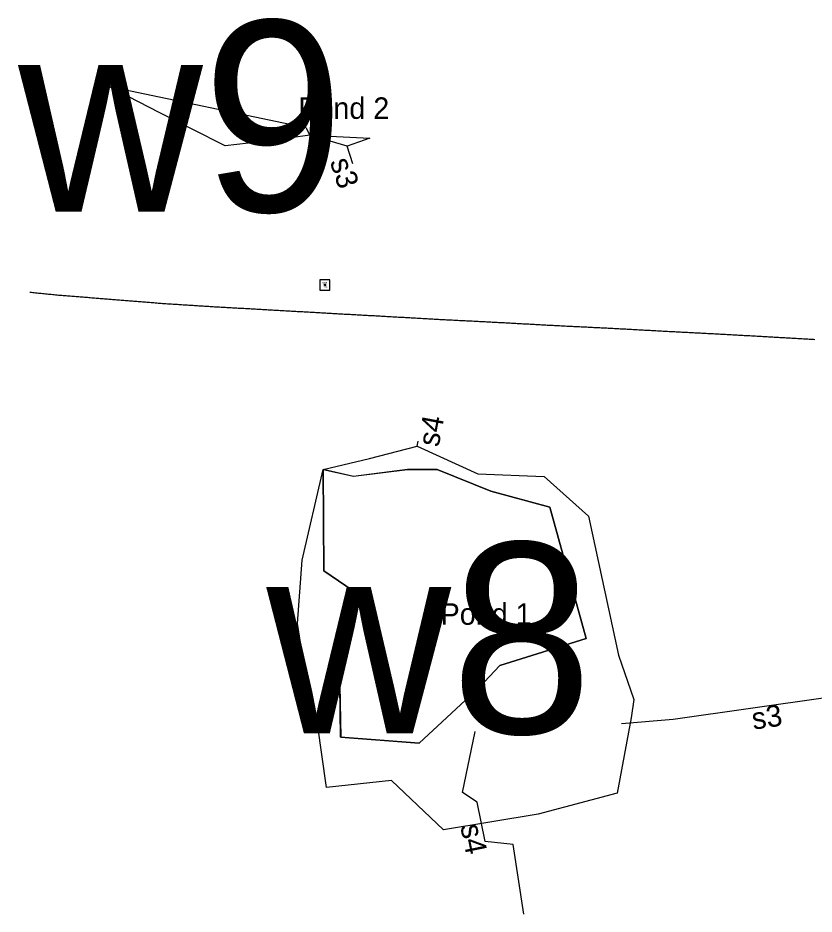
# Model space of a CAD drawing. Extents: x 205929 to 2357175, y -1785700 to 846739.
# Drawn here: x 2023790 to 2024346, y 813219 to 813844 of the extents above; entities that cross this region are included whole.
import ezdxf

# ---------------------------------------------------------------- set-up
doc = ezdxf.new("R2010")
doc.units = 0
for name, color, linetype in [('Default', 7, 'Continuous'), ('RD_EV_JTrib', 7, 'Continuous'), ('RD_EV_JW', 7, 'Continuous'), ('RD_EV_OWater', 7, 'Continuous'), ('RD_EV_TX', 7, 'Continuous'), ('RD_HC_Survey', 7, 'Continuous'), ('RD_HC_txCode', 7, 'Continuous'), ('RD_Sketch1', 7, 'Continuous'), ('RD_SMD_Locator', 7, 'Continuous')]:
    doc.layers.add(name, color=color, linetype=linetype)

# ---------------------------------------------------------------- blocks, each defined once
blk = doc.blocks.new('POL0003H')
at = {"layer": 'Default'}
blk.add_lwpolyline([(-28.23, 38.57), (-28.1, 20.59), (-21.57, 16.18), (-25.28, 0.31), (-25.1, -8.86), (-11.17, -9.92), (-0.58, -0.04), (3.12, 3.84), (18.42, 8.6), (11.94, 31.88), (1.53, 34.7), (-7.99, 38.58), (-13.28, 38.58), (-22.81, 37.35), (-28.23, 38.57), (-19.99, 40.51), (-11.56, 42.69), (-0.77, 37.81), (10.93, 37.3), (18.79, 30.28), (24.11, 5.68), (26.83, -2.21), (26.35, -5.46), (23.89, -18.77), (9.88, -22.48), (-6.88, -25.3), (-16.09, -16.51), (-27.63, -17.76), (-29.2, -6.5), (-31.05, 0.48), (-32.74, 11.27), (-31.92, 22.52)], close=True, dxfattribs=at)
blk = doc.blocks.new('POL0003I')
at = {"layer": 'Default'}
blk.add_lwpolyline([(16.05, -2.43), (9.29, -3.4), (1.03, -4.35), (-10.68, 1.57), (-19.69, 6.23), (15.36, -1.05)], close=True, dxfattribs=at)
blk = doc.blocks.new('ARC0002Y')
at = {"layer": 'Default'}
blk.add_lwpolyline([(30.39, -22.08), (18.78, -14.59), (8.16, -8.4), (4.67, 3.39), (-5.94, -4.32), (-33.35, -8.21), (-42.48, -8.95)], dxfattribs=at)
blk = doc.blocks.new('ARC0002Z')
at = {"layer": 'Default'}
blk.add_lwpolyline([(7.2, -14.7), (5.34, -2.35), (0.37, -1.82), (-1.05, 5.12), (-3.63, 6.86), (-1.37, 17.63)], dxfattribs=at)
blk = doc.blocks.new('ARC00030')
at = {"layer": 'Default'}
blk.add_lwpolyline([(-0.09, -0.46), (0.09, 0.46)], dxfattribs=at)
blk = doc.blocks.new('ARC00031')
at = {"layer": 'Default'}
blk.add_lwpolyline([(0.5, -1.54), (-0.5, 1.54)], dxfattribs=at)
blk = doc.blocks.new('POL0004D')
at = {"layer": 'Default'}
blk.add_lwpolyline([(0.86, -1.14), (-5.76, 0.83), (4.9, 0.31)], close=True, dxfattribs=at)
blk = doc.blocks.new('POL0004C')
at = {"layer": 'Default'}
blk.add_lwpolyline([(-20.42, 22.04), (-15, 20.82), (-5.48, 22.05), (-0.19, 22.05), (9.34, 18.17), (19.75, 15.35), (26.22, -7.93), (10.93, -12.7), (7.22, -16.58), (-3.36, -26.46), (-17.3, -25.4), (-17.47, -16.23), (-13.77, -0.35), (-20.3, 4.06)], close=True, dxfattribs=at)

msp = doc.modelspace()

# ---------------------------------------------------------------- linework, layer by layer
at = {"layer": 'RD_HC_Survey'}
msp.add_lwpolyline([(2024007.91, 813661.05), (2024000.84, 813661.05), (2024000.84, 813653.98), (2024007.91, 813653.98)], close=True, dxfattribs=at)
msp.add_circle((2024004.38, 813657.52), 0.5, dxfattribs=at)
at = {"layer": 'RD_Sketch1'}
msp.add_lwpolyline([(2023798.58, 813652.51), (2023799.57, 813652.41), (2023800.57, 813652.31), (2023801.56, 813652.21), (2023802.56, 813652.11), (2023803.55, 813652.01), (2023804.55, 813651.91), (2023805.54, 813651.81), (2023806.53, 813651.71), (2023807.53, 813651.61), (2023808.52, 813651.51), (2023809.52, 813651.41), (2023810.51, 813651.31), (2023811.51, 813651.21), (2023812.5, 813651.11), (2023813.5, 813651.01), (2023814.49, 813650.91), (2023815.49, 813650.81), (2023816.48, 813650.71), (2023817.48, 813650.61), (2023818.47, 813650.51), (2023818.77, 813650.48), (2023819.77, 813650.4), (2023820.76, 813650.32), (2023821.76, 813650.24), (2023822.76, 813650.16), (2023823.75, 813650.08), (2023824.75, 813650), (2023825.75, 813649.92), (2023826.74, 813649.84), (2023827.74, 813649.76), (2023828.74, 813649.68), (2023829.73, 813649.6), (2023830.73, 813649.52), (2023831.73, 813649.44), (2023832.72, 813649.37), (2023833.72, 813649.29), (2023834.72, 813649.21), (2023835.71, 813649.13), (2023836.71, 813649.05), (2023837.71, 813648.97), (2023838.7, 813648.89), (2023839.7, 813648.81), (2023840.7, 813648.73), (2023841.69, 813648.65), (2023842.69, 813648.57), (2023843.69, 813648.49), (2023844.68, 813648.41), (2023845.68, 813648.33), (2023846.68, 813648.25), (2023847.67, 813648.17), (2023848.67, 813648.09), (2023849.67, 813648.01), (2023850.66, 813647.94), (2023851.66, 813647.86), (2023852.66, 813647.78), (2023853.65, 813647.7), (2023854.18, 813647.65), (2023855.18, 813647.57), (2023856.18, 813647.49), (2023857.17, 813647.41), (2023858.17, 813647.33), (2023859.17, 813647.25), (2023860.16, 813647.17), (2023861.16, 813647.09), (2023861.16, 813647.09), (2023862.16, 813647.01), (2023863.15, 813646.93), (2023864.15, 813646.85), (2023865.15, 813646.77), (2023866.14, 813646.69), (2023867.14, 813646.61), (2023868.13, 813646.53), (2023869.13, 813646.45), (2023870.13, 813646.37), (2023871.12, 813646.29), (2023872.12, 813646.21), (2023873.12, 813646.13), (2023874.11, 813646.05), (2023875.11, 813645.97), (2023876.11, 813645.89), (2023877.1, 813645.81), (2023878.1, 813645.73), (2023879.1, 813645.65), (2023880.09, 813645.57), (2023881.09, 813645.49), (2023882.09, 813645.41), (2023883.08, 813645.33), (2023884.08, 813645.25), (2023885.08, 813645.17), (2023886.07, 813645.09), (2023887.07, 813645.01), (2023888.06, 813644.93), (2023889.06, 813644.85), (2023890.06, 813644.77), (2023891.05, 813644.69), (2023891.47, 813644.65), (2023892.47, 813644.59), (2023893.47, 813644.53), (2023894.47, 813644.46), (2023895.46, 813644.4), (2023896.46, 813644.34), (2023897.46, 813644.27), (2023898.46, 813644.21), (2023899.45, 813644.15), (2023900.45, 813644.08), (2023901.45, 813644.02), (2023902.45, 813643.96), (2023903.45, 813643.89), (2023904.44, 813643.83), (2023905.44, 813643.77), (2023906.44, 813643.7), (2023907.44, 813643.64), (2023908.43, 813643.58), (2023909.43, 813643.51), (2023910.43, 813643.45), (2023911.43, 813643.39), (2023912.43, 813643.32), (2023913.42, 813643.26), (2023914.42, 813643.2), (2023915.42, 813643.13), (2023916.42, 813643.07), (2023917.41, 813643.01), (2023918.41, 813642.94), (2023919.41, 813642.88), (2023920.41, 813642.82), (2023921.4, 813642.75), (2023922.4, 813642.69), (2023923.4, 813642.63), (2023924.4, 813642.56), (2023924.4, 813642.56), (2023925.4, 813642.5), (2023926.39, 813642.44), (2023927.39, 813642.37), (2023928.39, 813642.31), (2023928.93, 813642.28), (2023929.92, 813642.22), (2023930.92, 813642.17), (2023931.92, 813642.11), (2023932.92, 813642.05), (2023933.92, 813642), (2023934.92, 813641.94), (2023935.91, 813641.89), (2023936.91, 813641.83), (2023937.91, 813641.78), (2023938.91, 813641.72), (2023939.91, 813641.66), (2023940.91, 813641.61), (2023941.9, 813641.55), (2023942.9, 813641.5), (2023943.9, 813641.44), (2023944.9, 813641.39), (2023945.9, 813641.33), (2023946.9, 813641.27), (2023947.89, 813641.22), (2023948.89, 813641.16), (2023949.89, 813641.11), (2023950.89, 813641.05), (2023951.89, 813641), (2023952.89, 813640.94), (2023953.88, 813640.89), (2023954.88, 813640.83), (2023955.88, 813640.77), (2023956.88, 813640.72), (2023957.88, 813640.66), (2023958.88, 813640.61), (2023959.87, 813640.55), (2023960.87, 813640.5), (2023961.87, 813640.44), (2023962.87, 813640.38), (2023963.87, 813640.33), (2023964.87, 813640.27), (2023965.86, 813640.22), (2023966.86, 813640.16), (2023967.86, 813640.11), (2023968.86, 813640.05), (2023969.07, 813640.04), (2023970.07, 813639.98), (2023971.07, 813639.92), (2023972.06, 813639.87), (2023973.06, 813639.81), (2023974.06, 813639.75), (2023975.06, 813639.69), (2023976.06, 813639.64), (2023977.05, 813639.58), (2023978.05, 813639.52), (2023979.05, 813639.47), (2023980.05, 813639.41), (2023981.05, 813639.35), (2023982.04, 813639.29), (2023983.04, 813639.24), (2023984.04, 813639.18), (2023985.04, 813639.12), (2023986.04, 813639.06), (2023987.04, 813639.01), (2023987.04, 813639.01), (2023988.03, 813638.95), (2023989.03, 813638.89), (2023990.03, 813638.83), (2023991.03, 813638.78), (2023992.03, 813638.72), (2023993.02, 813638.66), (2023994.02, 813638.6), (2023995.02, 813638.55), (2023996.02, 813638.49), (2023997.02, 813638.43), (2023998.01, 813638.37), (2023999.01, 813638.32), (2024000.01, 813638.26), (2024001.01, 813638.2), (2024002.01, 813638.14), (2024003, 813638.09), (2024004, 813638.03), (2024005, 813637.97), (2024006, 813637.92), (2024007, 813637.86), (2024007.99, 813637.8), (2024008.99, 813637.74), (2024009.99, 813637.69), (2024010.92, 813637.63), (2024011.92, 813637.58), (2024012.91, 813637.52), (2024013.91, 813637.47), (2024014.91, 813637.41), (2024015.91, 813637.36), (2024016.91, 813637.3), (2024017.91, 813637.25), (2024018.9, 813637.19), (2024019.9, 813637.14), (2024020.9, 813637.08), (2024021.9, 813637.03), (2024022.9, 813636.97), (2024023.89, 813636.92), (2024024.89, 813636.86), (2024025.89, 813636.81), (2024026.89, 813636.75), (2024027.89, 813636.7), (2024028.89, 813636.65), (2024029.88, 813636.59), (2024030.88, 813636.54), (2024031.88, 813636.48), (2024032.88, 813636.43), (2024033.88, 813636.37), (2024034.87, 813636.32), (2024035.87, 813636.26), (2024036.87, 813636.21), (2024037.87, 813636.15), (2024038.87, 813636.1), (2024039.87, 813636.04), (2024040.86, 813635.99), (2024041.86, 813635.93), (2024042.86, 813635.88), (2024043.86, 813635.82), (2024044.86, 813635.77), (2024045.86, 813635.71), (2024046.68, 813635.67), (2024047.68, 813635.61), (2024048.67, 813635.56), (2024049.67, 813635.5), (2024050.67, 813635.44), (2024050.67, 813635.44), (2024051.67, 813635.39), (2024052.67, 813635.33), (2024053.66, 813635.27), (2024054.66, 813635.22), (2024055.66, 813635.16), (2024056.66, 813635.1), (2024057.66, 813635.05), (2024058.66, 813634.99), (2024059.65, 813634.94), (2024060.65, 813634.88), (2024061.65, 813634.82), (2024062.65, 813634.77), (2024063.65, 813634.71), (2024064.65, 813634.65), (2024065.64, 813634.6), (2024066.64, 813634.54), (2024067.64, 813634.48), (2024068.64, 813634.43), (2024069.64, 813634.37), (2024070.63, 813634.32), (2024071.63, 813634.26), (2024072.63, 813634.2), (2024073.63, 813634.15), (2024074.63, 813634.09), (2024075.63, 813634.03), (2024076.62, 813633.98), (2024077.62, 813633.92), (2024078.62, 813633.87), (2024079.62, 813633.81), (2024080.62, 813633.75), (2024081.62, 813633.7), (2024082.61, 813633.64), (2024083.61, 813633.58), (2024084.61, 813633.53), (2024085.25, 813633.49), (2024086.25, 813633.44), (2024087.25, 813633.39), (2024088.25, 813633.34), (2024089.25, 813633.29), (2024090.25, 813633.24), (2024091.24, 813633.19), (2024092.24, 813633.14), (2024093.24, 813633.09), (2024094.24, 813633.03), (2024095.24, 813632.98), (2024096.24, 813632.93), (2024097.23, 813632.88), (2024098.23, 813632.83), (2024099.23, 813632.78), (2024100.23, 813632.73), (2024101.23, 813632.68), (2024102.23, 813632.63), (2024103.22, 813632.58), (2024104.22, 813632.53), (2024105.22, 813632.48), (2024106.22, 813632.43), (2024107.22, 813632.38), (2024108.22, 813632.33), (2024109.21, 813632.27), (2024110.21, 813632.22), (2024111.21, 813632.17), (2024112.21, 813632.12), (2024113.21, 813632.07), (2024114.21, 813632.02), (2024114.21, 813632.02), (2024115.2, 813631.97), (2024116.2, 813631.92), (2024117.2, 813631.87), (2024118.2, 813631.82), (2024119.2, 813631.77), (2024120.2, 813631.72), (2024121.19, 813631.67), (2024122.19, 813631.62), (2024123.19, 813631.57), (2024124.19, 813631.51), (2024124.61, 813631.49), (2024125.6, 813631.44), (2024126.6, 813631.38), (2024127.6, 813631.33), (2024128.6, 813631.27), (2024129.6, 813631.22), (2024130.6, 813631.17), (2024131.59, 813631.11), (2024132.59, 813631.06), (2024133.59, 813631), (2024134.59, 813630.95), (2024135.59, 813630.89), (2024136.59, 813630.84), (2024137.58, 813630.78), (2024138.58, 813630.73), (2024139.58, 813630.67), (2024140.58, 813630.62), (2024141.58, 813630.57), (2024142.58, 813630.51), (2024143.57, 813630.46), (2024144.57, 813630.4), (2024145.57, 813630.35), (2024146.57, 813630.29), (2024147.57, 813630.24), (2024148.57, 813630.18), (2024149.56, 813630.13), (2024150.56, 813630.07), (2024151.56, 813630.02), (2024152.56, 813629.96), (2024153.56, 813629.91), (2024154.56, 813629.86), (2024155.56, 813629.8), (2024156.55, 813629.75), (2024157.55, 813629.69), (2024158.55, 813629.64), (2024159.55, 813629.58), (2024160.55, 813629.53), (2024161.55, 813629.47), (2024162.54, 813629.42), (2024163.54, 813629.36), (2024164.54, 813629.31), (2024165.13, 813629.28), (2024166.13, 813629.23), (2024167.13, 813629.18), (2024168.13, 813629.13), (2024169.13, 813629.08), (2024170.13, 813629.03), (2024171.13, 813628.98), (2024172.12, 813628.93), (2024173.12, 813628.88), (2024174.12, 813628.84), (2024175.12, 813628.79), (2024176.12, 813628.74), (2024177.12, 813628.69), (2024177.12, 813628.69), (2024178.12, 813628.64), (2024179.11, 813628.59), (2024180.11, 813628.54), (2024181.11, 813628.49), (2024182.11, 813628.44), (2024183.11, 813628.4), (2024184.11, 813628.35), (2024185.11, 813628.3), (2024186.11, 813628.25), (2024187.1, 813628.2), (2024188.1, 813628.15), (2024189.1, 813628.1), (2024190.1, 813628.05), (2024191.1, 813628), (2024192.1, 813627.95), (2024193.1, 813627.91), (2024194.09, 813627.86), (2024195.09, 813627.81), (2024196.09, 813627.76), (2024197.09, 813627.71), (2024198.09, 813627.66), (2024199.09, 813627.61), (2024200.09, 813627.56), (2024201.08, 813627.51), (2024202.08, 813627.47), (2024203.08, 813627.42), (2024204.08, 813627.37), (2024204.38, 813627.35), (2024205.38, 813627.3), (2024206.38, 813627.24), (2024207.38, 813627.19), (2024208.38, 813627.14), (2024209.38, 813627.08), (2024210.37, 813627.03), (2024211.37, 813626.97), (2024212.37, 813626.92), (2024213.37, 813626.86), (2024214.37, 813626.81), (2024215.37, 813626.76), (2024216.36, 813626.7), (2024217.36, 813626.65), (2024218.36, 813626.59), (2024219.36, 813626.54), (2024220.36, 813626.48), (2024221.35, 813626.43), (2024222.35, 813626.38), (2024223.35, 813626.32), (2024224.35, 813626.27), (2024225.35, 813626.21), (2024226.35, 813626.16), (2024227.34, 813626.1), (2024228.34, 813626.05), (2024229.34, 813625.99), (2024230.34, 813625.94), (2024231.34, 813625.89), (2024232.34, 813625.83), (2024233.33, 813625.78), (2024234.33, 813625.72), (2024235.33, 813625.67), (2024236.33, 813625.61), (2024237.33, 813625.56), (2024238.33, 813625.51), (2024239.32, 813625.45), (2024240.32, 813625.4), (2024240.32, 813625.4), (2024241.32, 813625.34), (2024242.32, 813625.29), (2024243.32, 813625.23), (2024243.49, 813625.23), (2024244.48, 813625.17), (2024245.48, 813625.12), (2024246.48, 813625.07), (2024247.48, 813625.02), (2024248.48, 813624.96), (2024249.48, 813624.91), (2024250.47, 813624.86), (2024251.47, 813624.81), (2024252.47, 813624.75), (2024253.47, 813624.7), (2024254.47, 813624.65), (2024255.47, 813624.6), (2024256.47, 813624.54), (2024257.46, 813624.49), (2024258.46, 813624.44), (2024259.46, 813624.39), (2024260.46, 813624.33), (2024261.46, 813624.28), (2024262.46, 813624.23), (2024263.45, 813624.18), (2024264.45, 813624.12), (2024265.45, 813624.07), (2024266.45, 813624.02), (2024267.45, 813623.97), (2024268.45, 813623.92), (2024269.44, 813623.86), (2024270.44, 813623.81), (2024271.44, 813623.76), (2024272.44, 813623.71), (2024273.44, 813623.65), (2024274.44, 813623.6), (2024275.43, 813623.55), (2024276.43, 813623.5), (2024277.43, 813623.44), (2024278.43, 813623.39), (2024279.43, 813623.34), (2024280.43, 813623.29), (2024281.43, 813623.23), (2024282.42, 813623.18), (2024282.94, 813623.15), (2024283.94, 813623.1), (2024284.94, 813623.04), (2024285.93, 813622.99), (2024286.93, 813622.93), (2024287.93, 813622.87), (2024288.93, 813622.82), (2024289.93, 813622.76), (2024290.93, 813622.71), (2024291.92, 813622.65), (2024292.92, 813622.59), (2024293.92, 813622.54), (2024294.92, 813622.48), (2024295.92, 813622.43), (2024296.92, 813622.37), (2024297.91, 813622.31), (2024298.91, 813622.26), (2024299.91, 813622.2), (2024300.91, 813622.15), (2024301.91, 813622.09), (2024302.91, 813622.03), (2024302.91, 813622.03), (2024303.9, 813621.98), (2024304.9, 813621.92), (2024305.9, 813621.87), (2024306.9, 813621.81), (2024307.9, 813621.75), (2024308.89, 813621.7), (2024309.89, 813621.64), (2024310.89, 813621.59), (2024311.89, 813621.53), (2024312.89, 813621.47), (2024313.89, 813621.42), (2024314.88, 813621.36), (2024315.88, 813621.31), (2024316.88, 813621.25), (2024317.88, 813621.19), (2024318.88, 813621.14), (2024319.88, 813621.08), (2024320.87, 813621.03), (2024321.87, 813620.97), (2024322.28, 813620.95), (2024323.28, 813620.89), (2024324.28, 813620.83), (2024325.28, 813620.78), (2024326.28, 813620.72), (2024327.27, 813620.66), (2024328.27, 813620.6), (2024329.27, 813620.54), (2024330.27, 813620.49), (2024331.27, 813620.43), (2024332.26, 813620.37), (2024333.26, 813620.31), (2024334.26, 813620.26), (2024335.26, 813620.2), (2024336.26, 813620.14), (2024337.25, 813620.08), (2024338.25, 813620.03), (2024339.25, 813619.97), (2024340.25, 813619.91), (2024341.25, 813619.85), (2024342.25, 813619.8), (2024343.24, 813619.74), (2024344.24, 813619.68), (2024345.24, 813619.62), (2024346.24, 813619.57)], dxfattribs=at)
at = {"layer": 'RD_SMD_Locator'}
msp.add_circle((2024004.38, 813657.52), 0.001, dxfattribs=at)

# ---------------------------------------------------------------- block references
at = {"layer": 'RD_EV_JTrib', "xscale": 3.937007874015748, "yscale": 3.937007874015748}
for name, p in [('ARC00031', (2024021.92, 813748.18)), ('ARC00030', (2024069.06, 813546.83)), ('ARC0002Y', (2024378.57, 813386.7)), ('ARC0002Z', (2024114.73, 813276.56))]:
    msp.add_blockref(name, p, dxfattribs=at)
at = {"layer": 'RD_EV_JW', "xscale": 3.937007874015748, "yscale": 3.937007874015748}
for name, p in [('POL0003I', (2023930.68, 813771.58)), ('POL0003H', (2024114.22, 813376.96))]:
    msp.add_blockref(name, p, dxfattribs=at)
at = {"layer": 'RD_EV_OWater', "xscale": 3.937007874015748, "yscale": 3.937007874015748}
for name, p in [('POL0004D', (2024016.55, 813758.74)), ('POL0004C', (2024083.49, 813442.06))]:
    msp.add_blockref(name, p, dxfattribs=at)

# ---------------------------------------------------------------- texts
at = {"layer": 'RD_EV_TX'}
for s, height, p in [('w9', 133.064, (2023790.46, 813708.75)), ('Pond 2', 15, (2023985.73, 813773.37)), ('w8', 133.064, (2023963.67, 813344.67)), ('Pond 1', 15, (2024085.09, 813420.49))]:
    msp.add_text(s, height=height, dxfattribs=at).set_placement(p)
for s, rotation, p in [('s3', 288.02357, (2024007.73, 813743.63)), ('s4', 79.34134, (2024083.69, 813544.01)), ('s3', 8.08411, (2024303.27, 813347.29)), ('s4', 281.59577, (2024098.79, 813280.13))]:
    msp.add_text(s, height=15, rotation=rotation, dxfattribs=at).set_placement(p)
at = {"layer": 'RD_HC_txCode'}
for s, p in [('8328', (2024002.75, 813658.52)), ('MSC', (2024003.06, 813655.52))]:
    msp.add_text(s, height=1, dxfattribs=at).set_placement(p)

doc.saveas('drawing.dxf')
